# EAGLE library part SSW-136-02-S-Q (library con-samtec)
THROUGH-HOLE .025" SQ POST SOCKET Source: Samtec SSW.pdf
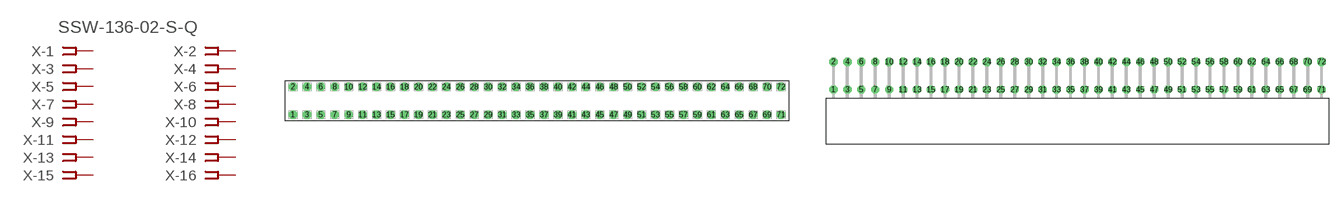
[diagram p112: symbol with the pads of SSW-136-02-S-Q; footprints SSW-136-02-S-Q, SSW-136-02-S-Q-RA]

Designator prefix X; gates -1=FPINV -2=FPIN -3=FPIN -4=FPIN -5=FPIN -6=FPIN -7=FPIN -8=FPIN -9=FPIN -10=FPIN -11=FPIN -12=FPIN -13=FPIN -14=FPIN -15=FPIN -16=FPIN -17=FPIN -18=FPIN -19=FPIN -20=FPIN -21=FPIN -22=FPIN -23=FPIN -24=FPIN -25=FPIN -26=FPIN -27=FPIN -28=FPIN -29=FPIN -30=FPIN -31=FPIN -32=FPIN -33=FPIN -34=FPIN -35=FPIN -36=FPIN -37=FPIN -38=FPIN -39=FPIN -40=FPIN -41=FPIN -42=FPIN -43=FPIN -44=FPIN -45=FPIN -46=FPIN -47=FPIN -48=FPIN -49=FPIN -50=FPIN -51=FPIN -52=FPIN -53=FPIN -54=FPIN -55=FPIN -56=FPIN -57=FPIN -58=FPIN -59=FPIN -60=FPIN -61=FPIN -62=FPIN -63=FPIN -64=FPIN -65=FPIN -66=FPIN -67=FPIN -68=FPIN -69=FPIN -70=FPIN -71=FPIN -72=FPIN

## SSW-136-02-S-Q (MPN: SSW-136-02-S-Q; OC_FARNELL: unknown; OC_NEWARK: 83P0978)  [SSW-136-02-S-Q]
1  -1:1  pas
2  -2:1  pas
3  -3:1  pas
4  -4:1  pas
5  -5:1  pas
6  -6:1  pas
7  -7:1  pas
8  -8:1  pas
9  -9:1  pas
10  -10:1  pas
11  -11:1  pas
12  -12:1  pas
13  -13:1  pas
14  -14:1  pas
15  -15:1  pas
16  -16:1  pas
17  -17:1  pas
18  -18:1  pas
19  -19:1  pas
20  -20:1  pas
21  -21:1  pas
22  -22:1  pas
23  -23:1  pas
24  -24:1  pas
25  -25:1  pas
26  -26:1  pas
27  -27:1  pas
28  -28:1  pas
29  -29:1  pas
30  -30:1  pas
31  -31:1  pas
32  -32:1  pas
33  -33:1  pas
34  -34:1  pas
35  -35:1  pas
36  -36:1  pas
37  -37:1  pas
38  -38:1  pas
39  -39:1  pas
40  -40:1  pas
41  -41:1  pas
42  -42:1  pas
43  -43:1  pas
44  -44:1  pas
45  -45:1  pas
46  -46:1  pas
47  -47:1  pas
48  -48:1  pas
49  -49:1  pas
50  -50:1  pas
51  -51:1  pas
52  -52:1  pas
53  -53:1  pas
54  -54:1  pas
55  -55:1  pas
56  -56:1  pas
57  -57:1  pas
58  -58:1  pas
59  -59:1  pas
60  -60:1  pas
61  -61:1  pas
62  -62:1  pas
63  -63:1  pas
64  -64:1  pas
65  -65:1  pas
66  -66:1  pas
67  -67:1  pas
68  -68:1  pas
69  -69:1  pas
70  -70:1  pas
71  -71:1  pas
72  -72:1  pas

## SSW-136-02-S-QRA (MPN: SSW-136-02-S-Q-RA; OC_FARNELL: unknown; OC_NEWARK: 83P0979)  [SSW-136-02-S-Q-RA]
Pads as for SSW-136-02-S-Q

## Footprint SSW-136-02-S-Q (pad centres in mm)
THROUGH-HOLE .025" SQ POST SOCKET Source: Samtec SSW.pdf
drill 1 pad 1.5 octagon: 1 -44.45,-2.54; 2 -44.45,2.54; 3 -41.91,-2.54; 4 -41.91,2.54; 5 -39.37,-2.54; 6 -39.37,2.54; 7 -36.83,-2.54; 8 -36.83,2.54; 9 -34.29,-2.54; 10 -34.29,2.54; 11 -31.75,-2.54; 12 -31.75,2.54; 13 -29.21,-2.54; 14 -29.21,2.54; 15 -26.67,-2.54; 16 -26.67,2.54; 17 -24.13,-2.54; 18 -24.13,2.54; 19 -21.59,-2.54; 20 -21.59,2.54; 21 -19.05,-2.54; 22 -19.05,2.54; 23 -16.51,-2.54; 24 -16.51,2.54; 25 -13.97,-2.54; 26 -13.97,2.54; 27 -11.43,-2.54; 28 -11.43,2.54; 29 -8.89,-2.54; 30 -8.89,2.54; 31 -6.35,-2.54; 32 -6.35,2.54; 33 -3.81,-2.54; 34 -3.81,2.54; 35 -1.27,-2.54; 36 -1.27,2.54; 37 1.27,-2.54; 38 1.27,2.54; 39 3.81,-2.54; 40 3.81,2.54; 41 6.35,-2.54; 42 6.35,2.54; 43 8.89,-2.54; 44 8.89,2.54; 45 11.43,-2.54; 46 11.43,2.54; 47 13.97,-2.54; 48 13.97,2.54; 49 16.51,-2.54; 50 16.51,2.54; 51 19.05,-2.54; 52 19.05,2.54; 53 21.59,-2.54; 54 21.59,2.54; 55 24.13,-2.54; 56 24.13,2.54; 57 26.67,-2.54; 58 26.67,2.54; 59 29.21,-2.54; 60 29.21,2.54; 61 31.75,-2.54; 62 31.75,2.54; 63 34.29,-2.54; 64 34.29,2.54; 65 36.83,-2.54; 66 36.83,2.54; 67 39.37,-2.54; 68 39.37,2.54; 69 41.91,-2.54; 70 41.91,2.54; 71 44.45,-2.54; 72 44.45,2.54

## Footprint SSW-136-02-S-Q-RA (pad centres in mm)
THROUGH-HOLE .025" SQ POST SOCKET Source: Samtec SSW.pdf
drill 1 pad 1.5 octagon: 1 -44.45,1.524; 2 -44.45,6.604; 3 -41.91,1.524; 4 -41.91,6.604; 5 -39.37,1.524; 6 -39.37,6.604; 7 -36.83,1.524; 8 -36.83,6.604; 9 -34.29,1.524; 10 -34.29,6.604; 11 -31.75,1.524; 12 -31.75,6.604; 13 -29.21,1.524; 14 -29.21,6.604; 15 -26.67,1.524; 16 -26.67,6.604; 17 -24.13,1.524; 18 -24.13,6.604; 19 -21.59,1.524; 20 -21.59,6.604; 21 -19.05,1.524; 22 -19.05,6.604; 23 -16.51,1.524; 24 -16.51,6.604; 25 -13.97,1.524; 26 -13.97,6.604; 27 -11.43,1.524; 28 -11.43,6.604; 29 -8.89,1.524; 30 -8.89,6.604; 31 -6.35,1.524; 32 -6.35,6.604; 33 -3.81,1.524; 34 -3.81,6.604; 35 -1.27,1.524; 36 -1.27,6.604; 37 1.27,1.524; 38 1.27,6.604; 39 3.81,1.524; 40 3.81,6.604; 41 6.35,1.524; 42 6.35,6.604; 43 8.89,1.524; 44 8.89,6.604; 45 11.43,1.524; 46 11.43,6.604; 47 13.97,1.524; 48 13.97,6.604; 49 16.51,1.524; 50 16.51,6.604; 51 19.05,1.524; 52 19.05,6.604; 53 21.59,1.524; 54 21.59,6.604; 55 24.13,1.524; 56 24.13,6.604; 57 26.67,1.524; 58 26.67,6.604; 59 29.21,1.524; 60 29.21,6.604; 61 31.75,1.524; 62 31.75,6.604; 63 34.29,1.524; 64 34.29,6.604; 65 36.83,1.524; 66 36.83,6.604; 67 39.37,1.524; 68 39.37,6.604; 69 41.91,1.524; 70 41.91,6.604; 71 44.45,1.524; 72 44.45,6.604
